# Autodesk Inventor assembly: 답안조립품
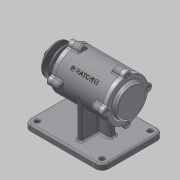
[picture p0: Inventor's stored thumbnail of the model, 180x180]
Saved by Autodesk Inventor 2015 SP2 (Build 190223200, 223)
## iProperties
Created: 2015-12
Part Number: 답안조립품
Document SubType Name: Assembly
Designer: AMC
Author: AMC
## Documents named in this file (11)
- C:\Users\AMC\Desktop\451207V1002\답안조립품.iam
- C:\Users\AMC\Desktop\451207V1002\본체.ipt
- C:\Users\AMC\Desktop\451207V1002\베어링 6204.ipt
- C:\Users\AMC\Desktop\451207V1002\볼트 M4 x 12.ipt
- C:\Users\AMC\Desktop\451207V1002\V-벨트풀리.ipt
- C:\Users\AMC\Desktop\451207V1002\너트 M12x1.25.ipt
- C:\Users\AMC\Desktop\451207V1002\커버.ipt
- C:\Users\AMC\Desktop\451207V1002\커버2.ipt
- C:\Users\AMC\Desktop\451207V1002\축.ipt
- C:\Users\AMC\Desktop\451207V1002\오일실.ipt
- C:\Users\AMC\Desktop\451207V1002\키(4 x 4 x 12).ipt
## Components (6 placed, 5 different names)
1. KS B 2023 6204 - 20 x 47 x 14:1
2. KS B 2023 6204 - 20 x 47 x 14:2
3. V-벨트풀리:1
4. KS B 1012 클래스 1 일반 - 미터 M12x1.25:1 — 각도:1
5. KS B 2804 D D - 20 32 8:1 — 플러쉬:1
6. KS B 1311 (I) 4 x 4 x 12:1
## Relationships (2: Flush 1, Angle 1)
- 플러쉬:1 [Flush]: KS B 2804 D D - 20 32 8:1
- 각도:1 [Angle]: KS B 1012 클래스 1 일반 - 미터 M12x1.25:1
